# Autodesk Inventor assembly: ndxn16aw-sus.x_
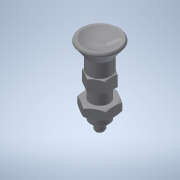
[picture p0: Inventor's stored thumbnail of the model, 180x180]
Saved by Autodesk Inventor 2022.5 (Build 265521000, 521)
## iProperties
Part Number: ndxn16aw-sus.x_
Material: 一般
Document SubType Name: Assembly
Designer: ImaoCorp
Sending System: SOLIDWORKS 2017-2017317
MC: AMD64
MC_MODEL: Intel64 Family 6 Model 60 Stepping 3, GenuineIntel
OS: Windows_NT
FRU: Parasolid Version 29.0, build 201,  4-17-2017
FORMAT: text
GUISE: transmit
KEY: ndxn16aw-sus
FILE: ndxn16aw-sus.x_t
DATE: Wed Sep 04 15:28:35 2019
Author: ImaoCorp
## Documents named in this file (3)
- X:\14_SW2022-Inv2022\00_全2023-1023新製品(TCC)まで\n\ndxn16aw-sus\NDXN16AW-SUS.iam
- X:\14_SW2022-Inv2022\00_全2023-1023新製品(TCC)まで\n\ndxn16aw-sus\ndxn16aw-sus_01.ipt
- X:\14_SW2022-Inv2022\00_全2023-1023新製品(TCC)まで\n\ndxn16aw-sus\ndxn16aw-sus_02.ipt
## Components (2 placed, 2 different names)
1. ndxn16aw-sus_01
2. ndxn16aw-sus_02
